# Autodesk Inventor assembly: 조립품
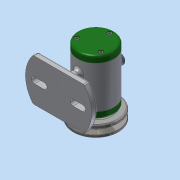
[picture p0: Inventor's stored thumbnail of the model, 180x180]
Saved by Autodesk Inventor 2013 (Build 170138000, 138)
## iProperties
Created: 2017-12
Part Number: 조립품
Document SubType Name: Assembly
Designer: dgall
Author: dgall
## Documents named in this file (14)
- C:\Users\dgall\Desktop\471207V1029\조립품.iam
- C:\Users\dgall\Desktop\471207V1029\본체.ipt
- C:\Users\dgall\Desktop\471207V1029\베어링 15 x 32 x 9.ipt
- C:\Users\dgall\Desktop\471207V1029\축.ipt
- C:\Users\dgall\Desktop\471207V1029\뒤커버.ipt
- C:\Users\dgall\Desktop\471207V1029\볼트 M4 x 12.ipt
- C:\Users\dgall\Desktop\471207V1029\오일 실 15 25 7.ipt
- C:\Users\dgall\Desktop\471207V1029\앞커버.ipt
- C:\Users\dgall\Desktop\471207V1029\V벨트풀리.ipt
- C:\Users\dgall\Desktop\471207V1029\키 3 x 3 x 12.ipt
- C:\Users\dgall\Desktop\471207V1029\너트 M 8.ipt
- C:\Users\dgall\Desktop\471207V1029\스프링와셔 8.ipt
- C:\Users\dgall\Desktop\471207V1029\와셔 8x17.ipt
- C:\Users\dgall\Desktop\471207V1029\고무캡.ipt
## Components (2 placed, 2 different names)
1. V벨트풀리:1
2. 고무캡:1
